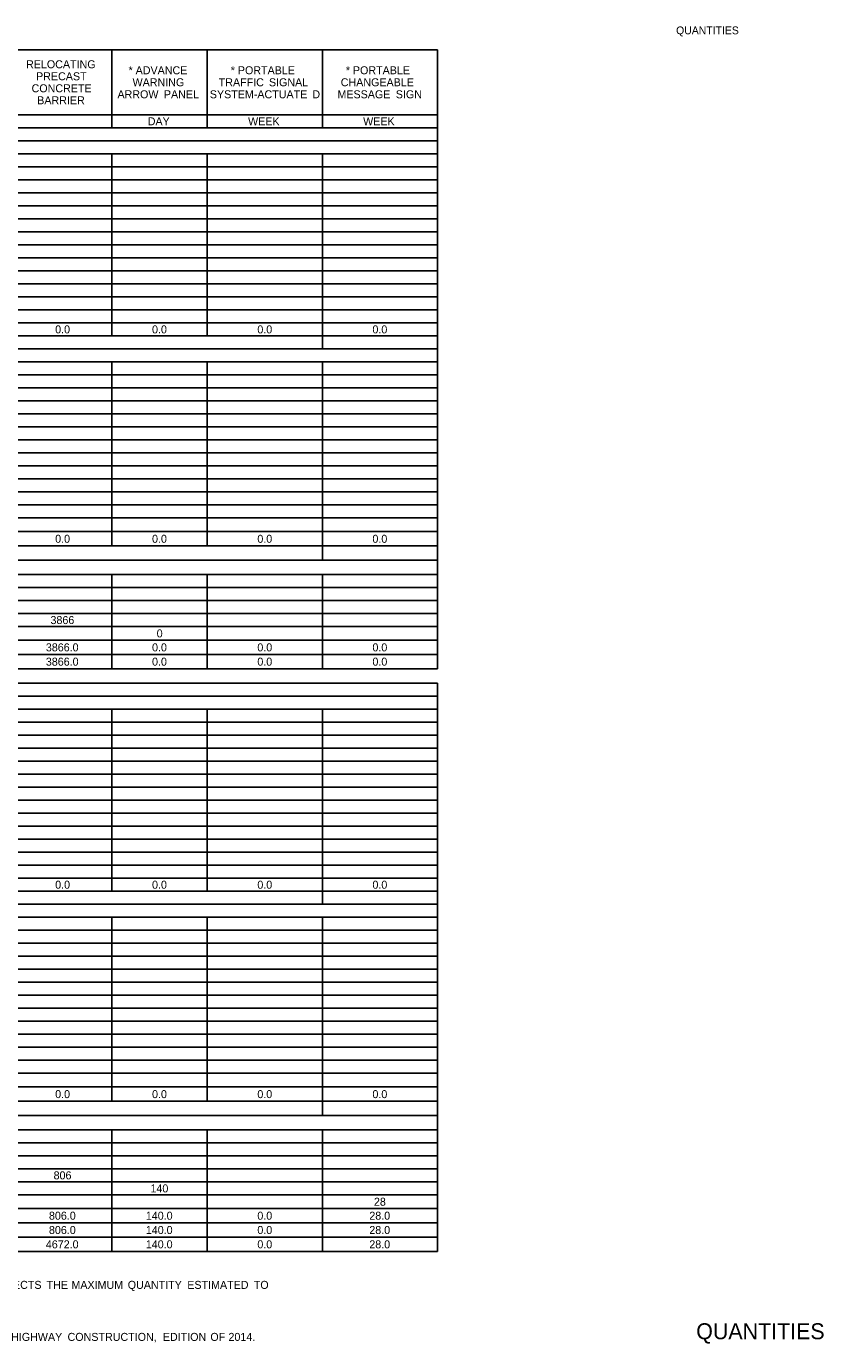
# Model space of a CAD drawing. Extents: x 540541 to 1930787, y -1948574 to 596640.
# Drawn here: x 541376 to 541974, y -1947044 to -1946056 of the extents above; entities that cross this region are included whole.
import ezdxf

# ---------------------------------------------------------------- set-up
doc = ezdxf.new("R2010")
doc.units = 0
for name, color, linetype in [('Default', 7, 'Continuous'), ('R_Border', 7, 'Continuous'), ('R_Border Prem', 7, 'Continuous')]:
    doc.layers.add(name, color=color, linetype=linetype)

msp = doc.modelspace()

# ---------------------------------------------------------------- linework, layer by layer
at = {"layer": 'Default'}
for p, q in [((540553.71, -1946074), (541684.22, -1946074)), ((541439.98, -1946132.5), (541439.98, -1946074)), ((541511.65, -1946132.5), (541511.65, -1946074)), ((541597.93, -1946132.5), (541597.93, -1946074)), ((541684.22, -1946122.75), (541684.22, -1946074)), ((541080.21, -1946122.75), (541684.22, -1946122.75)), ((541597.93, -1946132.5), (541597.93, -1946122.75)), ((541684.22, -1946152), (541684.22, -1946122.75)), ((540553.71, -1946132.5), (541684.22, -1946132.5)), ((541022.2, -1946132.5), (541684.22, -1946132.5)), ((540553.71, -1946142.25), (541684.22, -1946142.25)), ((540553.71, -1946152), (541684.22, -1946152)), ((541439.98, -1946269), (541439.98, -1946152)), ((541439.98, -1946288.5), (541439.98, -1946152)), ((541511.65, -1946288.5), (541511.65, -1946152)), ((541597.93, -1946298.25), (541597.93, -1946152)), ((541684.22, -1946298.25), (541684.22, -1946152)), ((540553.71, -1946161.75), (541684.22, -1946161.75)), ((540553.71, -1946171.5), (541684.22, -1946171.5)), ((540553.71, -1946181.25), (541684.22, -1946181.25)), ((540553.71, -1946191), (541684.22, -1946191)), ((540553.71, -1946200.75), (541684.22, -1946200.75)), ((540553.71, -1946210.5), (541684.22, -1946210.5)), ((540553.71, -1946220.25), (541684.22, -1946220.25)), ((540553.71, -1946230), (541684.22, -1946230)), ((540553.71, -1946239.75), (541684.22, -1946239.75)), ((540553.71, -1946249.5), (541684.22, -1946249.5)), ((540553.71, -1946259.25), (541684.22, -1946259.25)), ((540553.71, -1946269), (541684.22, -1946269)), ((541180.63, -1946278.75), (541684.22, -1946278.75)), ((541439.98, -1946288.5), (541439.98, -1946278.75)), ((541511.65, -1946288.5), (541511.65, -1946278.75)), ((540553.71, -1946288.5), (541684.22, -1946288.5)), ((541597.93, -1946298.25), (541597.93, -1946288.5)), ((540553.71, -1946298.25), (541684.22, -1946298.25)), ((541684.22, -1946308), (541684.22, -1946298.25)), ((540553.71, -1946308), (541684.22, -1946308)), ((541439.98, -1946445.96), (541439.98, -1946308)), ((541439.98, -1946445.96), (541439.98, -1946308)), ((541511.65, -1946445.96), (541511.65, -1946308)), ((541597.93, -1946456.69), (541597.93, -1946308)), ((541684.22, -1946538.1), (541684.22, -1946308)), ((540553.71, -1946317.75), (541684.22, -1946317.75)), ((540553.71, -1946327.5), (541684.22, -1946327.5)), ((540553.71, -1946337.25), (541684.22, -1946337.25)), ((540553.71, -1946347), (541684.22, -1946347)), ((540553.71, -1946356.75), (541684.22, -1946356.75)), ((540553.71, -1946366.5), (541684.22, -1946366.5)), ((540553.71, -1946376.25), (541684.22, -1946376.25)), ((540553.71, -1946386), (541684.22, -1946386)), ((540553.71, -1946395.75), (541684.22, -1946395.75)), ((540553.71, -1946405.5), (541684.22, -1946405.5)), ((540553.71, -1946415.25), (541684.22, -1946415.25)), ((540553.71, -1946425), (541684.22, -1946425)), ((540553.71, -1946435.24), (541684.22, -1946435.24)), ((540553.71, -1946435.24), (541684.22, -1946435.24)), ((541511.65, -1946445.96), (541511.65, -1946435.24)), ((540553.71, -1946445.96), (541684.22, -1946445.96)), ((541597.93, -1946456.69), (541597.93, -1946445.96)), ((540553.71, -1946456.69), (541684.22, -1946456.69)), ((540553.71, -1946467.41), (541684.22, -1946467.41)), ((541439.98, -1946486.91), (541439.98, -1946467.41)), ((541439.98, -1946538.1), (541439.98, -1946467.41)), ((541511.65, -1946538.1), (541511.65, -1946467.41)), ((541597.93, -1946538.1), (541597.93, -1946467.41)), ((540553.71, -1946477.16), (541684.22, -1946477.16)), ((540553.71, -1946486.91), (541684.22, -1946486.91)), ((541283.01, -1946496.66), (541684.22, -1946496.66)), ((541439.98, -1946538.1), (541439.98, -1946496.66)), ((540553.71, -1946506.41), (541684.22, -1946506.41)), ((540553.71, -1946516.65), (541684.22, -1946516.65)), ((540553.71, -1946516.65), (541684.22, -1946516.65)), ((541511.65, -1946538.1), (541511.65, -1946516.65)), ((540553.71, -1946527.38), (541684.22, -1946527.38)), ((540553.71, -1946538.1), (541684.22, -1946538.1)), ((540553.71, -1946548.83), (541684.22, -1946548.83)), ((541684.22, -1946568.33), (541684.22, -1946548.83)), ((540553.71, -1946558.58), (541684.22, -1946558.58)), ((540553.71, -1946568.33), (541684.22, -1946568.33)), ((541439.98, -1946685.33), (541439.98, -1946568.33)), ((541439.98, -1946704.83), (541439.98, -1946568.33)), ((541511.65, -1946704.83), (541511.65, -1946568.33)), ((541597.93, -1946714.58), (541597.93, -1946568.33)), ((541684.22, -1946714.58), (541684.22, -1946568.33)), ((540553.71, -1946578.08), (541684.22, -1946578.08)), ((540553.71, -1946587.83), (541684.22, -1946587.83)), ((540553.71, -1946597.58), (541684.22, -1946597.58)), ((540553.71, -1946607.33), (541684.22, -1946607.33)), ((540553.71, -1946617.08), (541684.22, -1946617.08)), ((540553.71, -1946626.83), (541684.22, -1946626.83)), ((540553.71, -1946636.58), (541684.22, -1946636.58)), ((540553.71, -1946646.33), (541684.22, -1946646.33)), ((540553.71, -1946656.08), (541684.22, -1946656.08)), ((540553.71, -1946665.83), (541684.22, -1946665.83)), ((540553.71, -1946675.58), (541684.22, -1946675.58)), ((540553.71, -1946685.33), (541684.22, -1946685.33)), ((541180.63, -1946695.08), (541684.22, -1946695.08)), ((541439.98, -1946704.83), (541439.98, -1946695.08)), ((541511.65, -1946704.83), (541511.65, -1946695.08)), ((540553.71, -1946704.83), (541684.22, -1946704.83)), ((541597.93, -1946714.58), (541597.93, -1946704.83)), ((540553.71, -1946714.58), (541684.22, -1946714.58)), ((541684.22, -1946724.33), (541684.22, -1946714.58)), ((540553.71, -1946724.33), (541684.22, -1946724.33)), ((541439.98, -1946862.29), (541439.98, -1946724.33)), ((541439.98, -1946862.29), (541439.98, -1946724.33)), ((541511.65, -1946862.29), (541511.65, -1946724.33)), ((541597.93, -1946873.01), (541597.93, -1946724.33)), ((541684.22, -1946974.9), (541684.22, -1946724.33)), ((540553.71, -1946734.08), (541684.22, -1946734.08)), ((540553.71, -1946743.83), (541684.22, -1946743.83)), ((540553.71, -1946753.58), (541684.22, -1946753.58)), ((540553.71, -1946763.33), (541684.22, -1946763.33)), ((540553.71, -1946773.08), (541684.22, -1946773.08)), ((540553.71, -1946782.83), (541684.22, -1946782.83)), ((540553.71, -1946792.58), (541684.22, -1946792.58)), ((540553.71, -1946802.33), (541684.22, -1946802.33)), ((540553.71, -1946812.08), (541684.22, -1946812.08)), ((540553.71, -1946821.83), (541684.22, -1946821.83)), ((540553.71, -1946831.58), (541684.22, -1946831.58)), ((540553.71, -1946841.33), (541684.22, -1946841.33)), ((540553.71, -1946851.56), (541684.22, -1946851.56)), ((540553.71, -1946851.56), (541684.22, -1946851.56)), ((541511.65, -1946862.29), (541511.65, -1946851.56)), ((540553.71, -1946862.29), (541684.22, -1946862.29)), ((541597.93, -1946873.01), (541597.93, -1946862.29)), ((540553.71, -1946873.01), (541684.22, -1946873.01)), ((540553.71, -1946883.74), (541684.22, -1946883.74)), ((541439.98, -1946903.24), (541439.98, -1946883.74)), ((541439.98, -1946974.9), (541439.98, -1946883.74)), ((541511.65, -1946974.9), (541511.65, -1946883.74)), ((541597.93, -1946974.9), (541597.93, -1946883.74)), ((540553.71, -1946893.49), (541684.22, -1946893.49)), ((540553.71, -1946903.24), (541684.22, -1946903.24)), ((541283.01, -1946912.99), (541684.22, -1946912.99)), ((541439.98, -1946974.9), (541439.98, -1946912.99)), ((540553.71, -1946922.74), (541684.22, -1946922.74)), ((540553.71, -1946932.49), (541684.22, -1946932.49)), ((540553.71, -1946942.73), (541597.93, -1946942.73)), ((540553.71, -1946942.73), (541684.22, -1946942.73)), ((541511.65, -1946974.9), (541511.65, -1946942.73)), ((541597.93, -1946942.73), (541684.22, -1946942.73)), ((540553.71, -1946953.45), (541684.22, -1946953.45)), ((540553.71, -1946964.18), (541684.22, -1946964.18)), ((541597.93, -1946974.9), (541597.93, -1946964.18)), ((540553.71, -1946974.9), (541684.22, -1946974.9))]:
    msp.add_line(p, q, dxfattribs=at)

# ---------------------------------------------------------------- texts
for s, p in [('RELOCATING', (541375.72, -1946087.88)), ('*', (541452.59, -1946092.38)), (' ADVANCE', (541455.67, -1946092.38)), ('*', (541529.23, -1946092.38)), (' PORTABLE', (541532.32, -1946092.38)), ('*', (541615.52, -1946092.38)), (' PORTABLE', (541618.6, -1946092.38)), ('PRECAST', (541383.23, -1946096.88)), ('WARNING', (541455.58, -1946101.38)), ('TRAFFIC', (541520.2, -1946101.38)), (' SIGNAL', (541555.63, -1946101.38)), ('CHANGEABLE', (541611.71, -1946101.38)), ('CONCRETE', (541379.86, -1946105.88)), ('ARROW', (541444.27, -1946110.38)), (' PANEL', (541476.86, -1946110.38)), ('SYSTEM-ACTUATE', (541513.52, -1946110.38)), ('D', (541590.42, -1946110.38)), ('MESSAGE', (541609.24, -1946110.38)), (' SIGN', (541650.76, -1946110.38)), ('BARRIER', (541384.1, -1946114.88)), ('DAY', (541466.96, -1946130.63)), ('WEEK', (541542.22, -1946130.63)), ('WEEK', (541628.51, -1946130.63)), ('0.0', (541397.56, -1946286.63)), ('0.0', (541470.2, -1946286.63)), ('0.0', (541549.17, -1946286.63)), ('0.0', (541635.46, -1946286.63)), ('0.0', (541397.56, -1946443.6)), ('0.0', (541470.2, -1946443.6)), ('0.0', (541549.17, -1946443.6)), ('0.0', (541635.46, -1946443.6)), ('3866', (541394.05, -1946504.54)), ('0', (541473.69, -1946514.53)), ('3866.0', (541390.57, -1946525.01)), ('0.0', (541470.2, -1946525.01)), ('0.0', (541549.17, -1946525.01)), ('0.0', (541635.46, -1946525.01)), ('3866.0', (541390.57, -1946535.74)), ('0.0', (541470.2, -1946535.74)), ('0.0', (541549.17, -1946535.74)), ('0.0', (541635.46, -1946535.74)), ('0.0', (541397.56, -1946702.95)), ('0.0', (541470.2, -1946702.95)), ('0.0', (541549.17, -1946702.95)), ('0.0', (541635.46, -1946702.95)), ('0.0', (541397.56, -1946859.93)), ('0.0', (541470.2, -1946859.93)), ('0.0', (541549.17, -1946859.93)), ('0.0', (541635.46, -1946859.93)), ('806', (541396.38, -1946920.86)), ('140', (541469.03, -1946930.61)), ('28', (541636.6, -1946940.61)), ('806.0', (541392.9, -1946951.09)), ('140.0', (541465.54, -1946951.09)), ('0.0', (541549.17, -1946951.09)), ('28.0', (541633.13, -1946951.09)), ('806.0', (541392.9, -1946961.81)), ('140.0', (541465.54, -1946961.81)), ('0.0', (541549.17, -1946961.81)), ('28.0', (541633.13, -1946961.81)), ('4672.0', (541390.57, -1946972.54)), ('140.0', (541465.54, -1946972.54)), ('0.0', (541549.17, -1946972.54)), ('28.0', (541633.13, -1946972.54)), (' REFLECTS', (541343.2, -1947002.95)), (' THE', (541388.88, -1947002.95)), (' MAXIMUM', (541407.53, -1947002.95)), (' QUANTITY', (541449.75, -1947002.95)), (' ESTIMATED', (541494.4, -1947002.95)), (' TO', (541544.26, -1947002.95)), (' HIGHWAY', (541362.29, -1947041.95)), (' CONSTRUCTION,', (541404.61, -1947041.95)), (' EDITION', (541476.06, -1947041.95)), (' OF', (541511.7, -1947041.95)), (' 2014.', (541525.29, -1947041.95))]:
    msp.add_text(s, height=6, dxfattribs=at).set_placement(p)
at = {"layer": 'R_Border'}
msp.add_text('QUANTITIES', height=12, rotation=360, dxfattribs=at).set_placement((541878.29, -1947040.71))
at = {"layer": 'R_Border Prem'}
msp.add_text('QUANTITIES', height=5.862, rotation=360, dxfattribs=at).set_placement((541863.19, -1946062.39))

doc.saveas('drawing.dxf')
